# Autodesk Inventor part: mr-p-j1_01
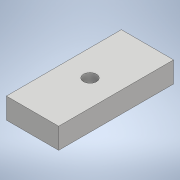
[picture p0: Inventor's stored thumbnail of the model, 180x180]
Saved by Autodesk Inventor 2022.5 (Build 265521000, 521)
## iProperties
Part Number: mr-p-j1_01
Material: 一般
Document SubType Name: Modeling
Designer: ImaoCorp
Density: 1 g/cm^3
Appearance: 既定
Author: ImaoCorp
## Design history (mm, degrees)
feature "mr-p-j1_01"
node "ソリッド1"
